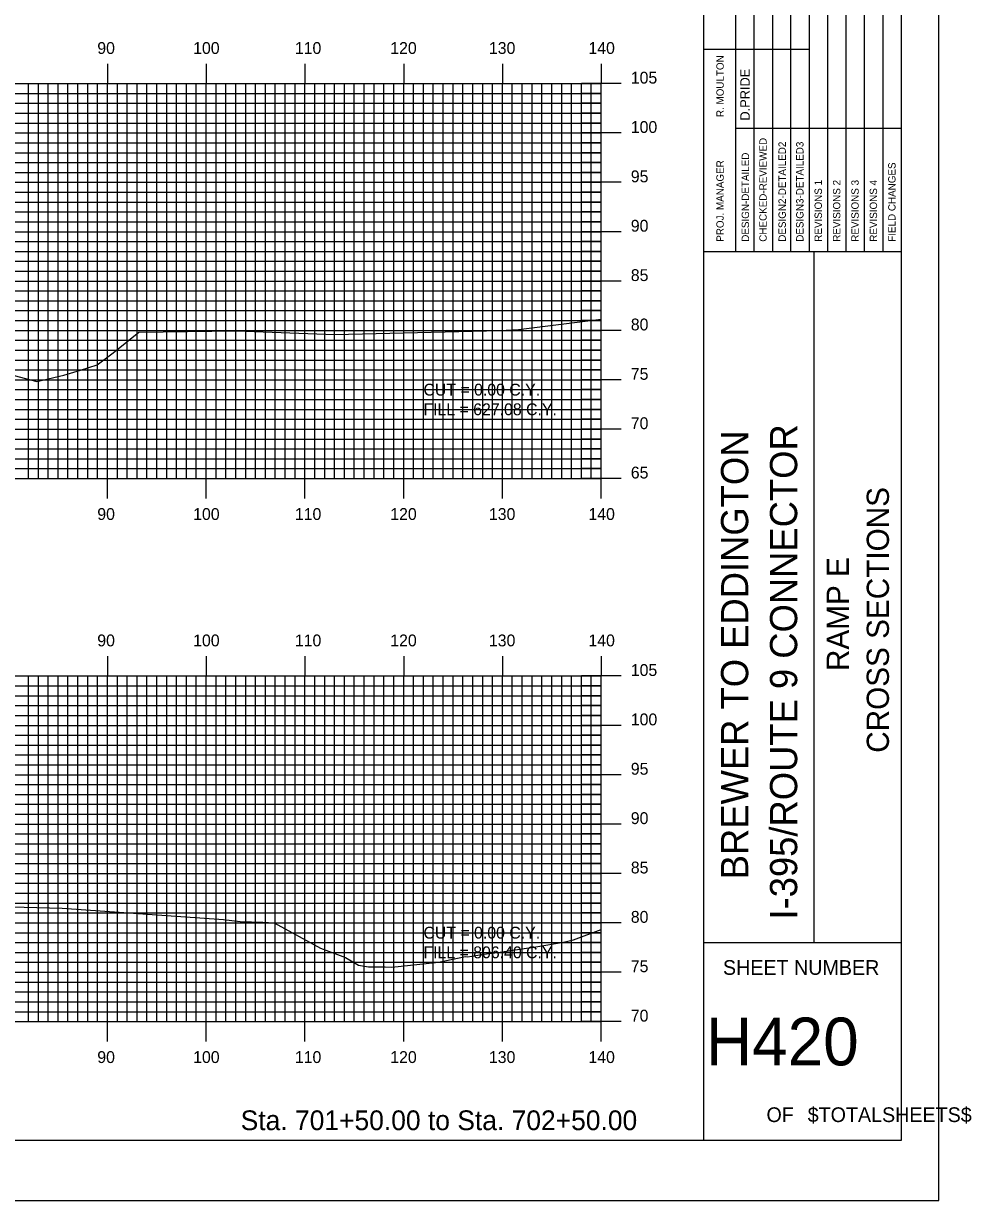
# Model space of a CAD drawing. Extents: x 852936 to 853279, y 364366 to 364586.
# Drawn here: x 853183.2 to 853279.2, y 364365.7 to 364484.9 of the extents above; entities that cross this region are included whole.
import ezdxf

# ---------------------------------------------------------------- set-up
doc = ezdxf.new("R2010")
doc.units = 0
for name, color, linetype in [('BORDER', 7, 'Continuous'), ('D_Text_Standard', 7, 'Continuous'), ('H_V ANNOTATION', 7, 'Continuous'), ('MAJOR', 7, 'Continuous'), ('MINOR', 7, 'Continuous'), ('PLOT BOUNDARY', 7, 'Continuous'), ('S_Roadway_Centerline', 7, 'Continuous')]:
    doc.layers.add(name, color=color, linetype=linetype)

msp = doc.modelspace()

# ---------------------------------------------------------------- linework, layer by layer
at = {"layer": 'BORDER'}
for p, q in [((853252.09, 364371.79), (853252.09, 364581.79)), ((853252.09, 364461.79), (853272.09, 364461.79)), ((853263.27, 364391.79), (853263.27, 364461.79)), ((853252.09, 364391.79), (853272.09, 364391.79))]:
    msp.add_line(p, q, dxfattribs=at)
msp.add_lwpolyline([(852952.09, 364371.79), (853272.09, 364371.79), (853272.09, 364581.79), (852952.09, 364581.79)], close=True, dxfattribs=at)
for points in [[(853257.19, 364461.8), (853257.19, 364496.79)], [(853259.05, 364496.79), (853259.05, 364461.8)], [(853260.91, 364461.8), (853260.91, 364496.79)], [(853262.78, 364461.8), (853262.78, 364496.79)], [(853264.64, 364461.8), (853264.64, 364496.79)], [(853266.5, 364461.8), (853266.5, 364496.79)], [(853268.37, 364461.8), (853268.37, 364496.79)], [(853270.23, 364461.8), (853270.23, 364496.79)], [(853255.32, 364461.8), (853255.32, 364495.38)], [(853252.09, 364482.29), (853255.32, 364482.29)], [(853255.32, 364482.29), (853262.77, 364482.29)], [(853255.32, 364474.29), (853272.09, 364474.29)]]:
    msp.add_lwpolyline(points, dxfattribs=at)
at = {"layer": 'MAJOR'}
for p, q in [((853191.69, 364480.79), (853191.69, 364478.79)), ((853201.69, 364480.79), (853201.69, 364478.79)), ((853211.69, 364480.79), (853211.69, 364478.79)), ((853221.69, 364480.79), (853221.69, 364478.79)), ((853231.69, 364480.79), (853231.69, 364478.79)), ((853241.69, 364480.79), (853241.69, 364478.79)), ((852961.69, 364478.79), (853241.69, 364478.79)), ((852961.69, 364478.79), (853241.69, 364478.79)), ((853191.69, 364438.79), (853191.69, 364478.79)), ((853201.69, 364438.79), (853201.69, 364478.79)), ((853211.69, 364438.79), (853211.69, 364478.79)), ((853221.69, 364438.79), (853221.69, 364478.79)), ((853231.69, 364438.79), (853231.69, 364478.79)), ((853243.7, 364478.79), (853239.69, 364478.79)), ((853241.69, 364438.79), (853241.69, 364478.79)), ((853241.69, 364438.79), (853241.69, 364478.79)), ((852961.69, 364473.79), (853241.69, 364473.79)), ((853243.7, 364473.79), (853239.69, 364473.79)), ((852961.69, 364468.79), (853241.69, 364468.79)), ((853243.7, 364468.79), (853239.69, 364468.79)), ((852961.69, 364463.79), (853241.69, 364463.79)), ((853243.7, 364463.79), (853239.69, 364463.79)), ((852961.69, 364458.79), (853241.69, 364458.79)), ((853243.7, 364458.79), (853239.69, 364458.79)), ((852961.69, 364453.79), (853241.69, 364453.79)), ((853243.7, 364453.79), (853239.69, 364453.79)), ((852961.69, 364448.79), (853241.69, 364448.79)), ((853243.7, 364448.79), (853239.69, 364448.79)), ((852961.69, 364443.79), (853241.69, 364443.79)), ((853243.7, 364443.79), (853239.69, 364443.79)), ((852961.69, 364438.79), (853241.69, 364438.79)), ((852961.69, 364438.79), (853241.69, 364438.79)), ((853191.69, 364436.78), (853191.69, 364438.79)), ((853201.69, 364436.78), (853201.69, 364438.79)), ((853211.69, 364436.78), (853211.69, 364438.79)), ((853221.69, 364436.78), (853221.69, 364438.79)), ((853231.69, 364436.78), (853231.69, 364438.79)), ((853243.7, 364438.79), (853239.69, 364438.79)), ((853241.69, 364436.78), (853241.69, 364438.79)), ((853191.69, 364420.79), (853191.69, 364418.79)), ((853201.69, 364420.79), (853201.69, 364418.79)), ((853211.69, 364420.79), (853211.69, 364418.79)), ((853221.69, 364420.79), (853221.69, 364418.79)), ((853231.69, 364420.79), (853231.69, 364418.79)), ((853241.69, 364420.79), (853241.69, 364418.79)), ((852961.69, 364418.79), (853241.69, 364418.79)), ((852961.69, 364418.79), (853241.69, 364418.79)), ((853191.69, 364383.79), (853191.69, 364418.79)), ((853201.69, 364383.79), (853201.69, 364418.79)), ((853211.69, 364383.79), (853211.69, 364418.79)), ((853221.69, 364383.79), (853221.69, 364418.79)), ((853231.69, 364383.79), (853231.69, 364418.79)), ((853243.7, 364418.79), (853239.69, 364418.79)), ((853241.69, 364383.79), (853241.69, 364418.79)), ((853241.69, 364383.79), (853241.69, 364418.79)), ((852961.69, 364413.79), (853241.69, 364413.79)), ((853243.7, 364413.79), (853239.69, 364413.79)), ((852961.69, 364408.79), (853241.69, 364408.79)), ((853243.7, 364408.79), (853239.69, 364408.79)), ((852961.69, 364403.79), (853241.69, 364403.79)), ((853243.7, 364403.79), (853239.69, 364403.79)), ((852961.69, 364398.79), (853241.69, 364398.79)), ((853243.7, 364398.79), (853239.69, 364398.79)), ((852961.69, 364393.79), (853241.69, 364393.79)), ((853243.7, 364393.79), (853239.69, 364393.79)), ((852961.69, 364388.79), (853241.69, 364388.79)), ((853243.7, 364388.79), (853239.69, 364388.79)), ((852961.69, 364383.79), (853241.69, 364383.79)), ((852961.69, 364383.79), (853241.69, 364383.79)), ((853191.69, 364381.78), (853191.69, 364383.79)), ((853201.69, 364381.78), (853201.69, 364383.79)), ((853211.69, 364381.78), (853211.69, 364383.79)), ((853221.69, 364381.78), (853221.69, 364383.79)), ((853231.69, 364381.78), (853231.69, 364383.79)), ((853243.7, 364383.79), (853239.69, 364383.79)), ((853241.69, 364381.78), (853241.69, 364383.79))]:
    msp.add_line(p, q, dxfattribs=at)
at = {"layer": 'MINOR'}
for p, q in [((853183.69, 364438.79), (853183.69, 364478.79)), ((853184.69, 364438.79), (853184.69, 364478.79)), ((853185.69, 364438.79), (853185.69, 364478.79)), ((853186.69, 364438.79), (853186.69, 364478.79)), ((853187.69, 364438.79), (853187.69, 364478.79)), ((853188.69, 364438.79), (853188.69, 364478.79)), ((853189.69, 364438.79), (853189.69, 364478.79)), ((853190.69, 364438.79), (853190.69, 364478.79)), ((853192.69, 364438.79), (853192.69, 364478.79)), ((853193.69, 364438.79), (853193.69, 364478.79)), ((853194.69, 364438.79), (853194.69, 364478.79)), ((853195.69, 364438.79), (853195.69, 364478.79)), ((853196.69, 364438.79), (853196.69, 364478.79)), ((853197.69, 364438.79), (853197.69, 364478.79)), ((853198.69, 364438.79), (853198.69, 364478.79)), ((853199.69, 364438.79), (853199.69, 364478.79)), ((853200.69, 364438.79), (853200.69, 364478.79)), ((853202.69, 364438.79), (853202.69, 364478.79)), ((853203.69, 364438.79), (853203.69, 364478.79)), ((853204.69, 364438.79), (853204.69, 364478.79)), ((853205.69, 364438.79), (853205.69, 364478.79)), ((853206.69, 364438.79), (853206.69, 364478.79)), ((853207.69, 364438.79), (853207.69, 364478.79)), ((853208.69, 364438.79), (853208.69, 364478.79)), ((853209.69, 364438.79), (853209.69, 364478.79)), ((853210.69, 364438.79), (853210.69, 364478.79)), ((853212.69, 364438.79), (853212.69, 364478.79)), ((853213.69, 364438.79), (853213.69, 364478.79)), ((853214.69, 364438.79), (853214.69, 364478.79)), ((853215.69, 364438.79), (853215.69, 364478.79)), ((853216.69, 364438.79), (853216.69, 364478.79)), ((853217.69, 364438.79), (853217.69, 364478.79)), ((853218.69, 364438.79), (853218.69, 364478.79)), ((853219.69, 364438.79), (853219.69, 364478.79)), ((853220.69, 364438.79), (853220.69, 364478.79)), ((853222.69, 364438.79), (853222.69, 364478.79)), ((853223.69, 364438.79), (853223.69, 364478.79)), ((853224.69, 364438.79), (853224.69, 364478.79)), ((853225.69, 364438.79), (853225.69, 364478.79)), ((853226.69, 364438.79), (853226.69, 364478.79)), ((853227.69, 364438.79), (853227.69, 364478.79)), ((853228.69, 364438.79), (853228.69, 364478.79)), ((853229.69, 364438.79), (853229.69, 364478.79)), ((853230.69, 364438.79), (853230.69, 364478.79)), ((853232.69, 364438.79), (853232.69, 364478.79)), ((853233.69, 364438.79), (853233.69, 364478.79)), ((853234.69, 364438.79), (853234.69, 364478.79)), ((853235.69, 364438.79), (853235.69, 364478.79)), ((853236.69, 364438.79), (853236.69, 364478.79)), ((853237.69, 364438.79), (853237.69, 364478.79)), ((853238.69, 364438.79), (853238.69, 364478.79)), ((853239.69, 364438.79), (853239.69, 364478.79)), ((853240.69, 364438.79), (853240.69, 364478.79)), ((852961.69, 364477.79), (853241.69, 364477.79)), ((852961.69, 364476.79), (853241.69, 364476.79)), ((853241.69, 364477.79), (853239.69, 364477.79)), ((853241.69, 364476.79), (853239.69, 364476.79)), ((852961.69, 364475.79), (853241.69, 364475.79)), ((853241.69, 364475.79), (853239.69, 364475.79)), ((852961.69, 364474.79), (853241.69, 364474.79)), ((853241.69, 364474.79), (853239.69, 364474.79)), ((852961.69, 364472.79), (853241.69, 364472.79)), ((853241.69, 364472.79), (853239.69, 364472.79)), ((852961.69, 364471.79), (853241.69, 364471.79)), ((852961.69, 364470.79), (853241.69, 364470.79)), ((853241.69, 364471.79), (853239.69, 364471.79)), ((853241.69, 364470.79), (853239.69, 364470.79)), ((852961.69, 364469.79), (853241.69, 364469.79)), ((853241.69, 364469.79), (853239.69, 364469.79)), ((852961.69, 364467.79), (853241.69, 364467.79)), ((853241.69, 364467.79), (853239.69, 364467.79)), ((852961.69, 364466.79), (853241.69, 364466.79)), ((853241.69, 364466.79), (853239.69, 364466.79)), ((852961.69, 364465.79), (853241.69, 364465.79)), ((853241.69, 364465.79), (853239.69, 364465.79)), ((852961.69, 364464.79), (853241.69, 364464.79)), ((853241.69, 364464.79), (853239.69, 364464.79)), ((852961.69, 364462.79), (853241.69, 364462.79)), ((853241.69, 364462.79), (853239.69, 364462.79)), ((852961.69, 364461.79), (853241.69, 364461.79)), ((853241.69, 364461.79), (853239.69, 364461.79)), ((852961.69, 364460.79), (853241.69, 364460.79)), ((853241.69, 364460.79), (853239.69, 364460.79)), ((852961.69, 364459.79), (853241.69, 364459.79)), ((853241.69, 364459.79), (853239.69, 364459.79)), ((852961.69, 364457.79), (853241.69, 364457.79)), ((853241.69, 364457.79), (853239.69, 364457.79)), ((852961.69, 364456.79), (853241.69, 364456.79)), ((853241.69, 364456.79), (853239.69, 364456.79)), ((852961.69, 364455.79), (853241.69, 364455.79)), ((853241.69, 364455.79), (853239.69, 364455.79)), ((852961.69, 364454.79), (853241.69, 364454.79)), ((853241.69, 364454.79), (853239.69, 364454.79)), ((852961.69, 364452.79), (853241.69, 364452.79)), ((852961.69, 364451.79), (853241.69, 364451.79)), ((853241.69, 364452.79), (853239.69, 364452.79)), ((853241.69, 364451.79), (853239.69, 364451.79)), ((852961.69, 364450.79), (853241.69, 364450.79)), ((853241.69, 364450.79), (853239.69, 364450.79)), ((852961.69, 364449.79), (853241.69, 364449.79)), ((853241.69, 364449.79), (853239.69, 364449.79)), ((852961.69, 364447.79), (853241.69, 364447.79)), ((853241.69, 364447.79), (853239.69, 364447.79)), ((852961.69, 364446.79), (853241.69, 364446.79)), ((852961.69, 364445.79), (853241.69, 364445.79)), ((853241.69, 364446.79), (853239.69, 364446.79)), ((853241.69, 364445.79), (853239.69, 364445.79)), ((852961.69, 364444.79), (853241.69, 364444.79)), ((853241.69, 364444.79), (853239.69, 364444.79)), ((852961.69, 364442.79), (853241.69, 364442.79)), ((853241.69, 364442.79), (853239.69, 364442.79)), ((852961.69, 364441.79), (853241.69, 364441.79)), ((853241.69, 364441.79), (853239.69, 364441.79)), ((852961.69, 364440.79), (853241.69, 364440.79)), ((853241.69, 364440.79), (853239.69, 364440.79)), ((852961.69, 364439.79), (853241.69, 364439.79)), ((853241.69, 364439.79), (853239.69, 364439.79)), ((853183.69, 364383.79), (853183.69, 364418.79)), ((853184.69, 364383.79), (853184.69, 364418.79)), ((853185.69, 364383.79), (853185.69, 364418.79)), ((853186.69, 364383.79), (853186.69, 364418.79)), ((853187.69, 364383.79), (853187.69, 364418.79)), ((853188.69, 364383.79), (853188.69, 364418.79)), ((853189.69, 364383.79), (853189.69, 364418.79)), ((853190.69, 364383.79), (853190.69, 364418.79)), ((853192.69, 364383.79), (853192.69, 364418.79)), ((853193.69, 364383.79), (853193.69, 364418.79)), ((853194.69, 364383.79), (853194.69, 364418.79)), ((853195.69, 364383.79), (853195.69, 364418.79)), ((853196.69, 364383.79), (853196.69, 364418.79)), ((853197.69, 364383.79), (853197.69, 364418.79)), ((853198.69, 364383.79), (853198.69, 364418.79)), ((853199.69, 364383.79), (853199.69, 364418.79)), ((853200.69, 364383.79), (853200.69, 364418.79)), ((853202.69, 364383.79), (853202.69, 364418.79)), ((853203.69, 364383.79), (853203.69, 364418.79)), ((853204.69, 364383.79), (853204.69, 364418.79)), ((853205.69, 364383.79), (853205.69, 364418.79)), ((853206.69, 364383.79), (853206.69, 364418.79)), ((853207.69, 364383.79), (853207.69, 364418.79)), ((853208.69, 364383.79), (853208.69, 364418.79)), ((853209.69, 364383.79), (853209.69, 364418.79)), ((853210.69, 364383.79), (853210.69, 364418.79)), ((853212.69, 364383.79), (853212.69, 364418.79)), ((853213.69, 364383.79), (853213.69, 364418.79)), ((853214.69, 364383.79), (853214.69, 364418.79)), ((853215.69, 364383.79), (853215.69, 364418.79)), ((853216.69, 364383.79), (853216.69, 364418.79)), ((853217.69, 364383.79), (853217.69, 364418.79)), ((853218.69, 364383.79), (853218.69, 364418.79)), ((853219.69, 364383.79), (853219.69, 364418.79)), ((853220.69, 364383.79), (853220.69, 364418.79)), ((853222.69, 364383.79), (853222.69, 364418.79)), ((853223.69, 364383.79), (853223.69, 364418.79)), ((853224.69, 364383.79), (853224.69, 364418.79)), ((853225.69, 364383.79), (853225.69, 364418.79)), ((853226.69, 364383.79), (853226.69, 364418.79)), ((853227.69, 364383.79), (853227.69, 364418.79)), ((853228.69, 364383.79), (853228.69, 364418.79)), ((853229.69, 364383.79), (853229.69, 364418.79)), ((853230.69, 364383.79), (853230.69, 364418.79)), ((853232.69, 364383.79), (853232.69, 364418.79)), ((853233.69, 364383.79), (853233.69, 364418.79)), ((853234.69, 364383.79), (853234.69, 364418.79)), ((853235.69, 364383.79), (853235.69, 364418.79)), ((853236.69, 364383.79), (853236.69, 364418.79)), ((853237.69, 364383.79), (853237.69, 364418.79)), ((853238.69, 364383.79), (853238.69, 364418.79)), ((853239.69, 364383.79), (853239.69, 364418.79)), ((853240.69, 364383.79), (853240.69, 364418.79)), ((852961.69, 364417.79), (853241.69, 364417.79)), ((853241.69, 364417.79), (853239.69, 364417.79)), ((852961.69, 364416.79), (853241.69, 364416.79)), ((853241.69, 364416.79), (853239.69, 364416.79)), ((852961.69, 364415.79), (853241.69, 364415.79)), ((852961.69, 364414.79), (853241.69, 364414.79)), ((853241.69, 364415.79), (853239.69, 364415.79)), ((853241.69, 364414.79), (853239.69, 364414.79)), ((852961.69, 364412.79), (853241.69, 364412.79)), ((853241.69, 364412.79), (853239.69, 364412.79)), ((852961.69, 364411.79), (853241.69, 364411.79)), ((853241.69, 364411.79), (853239.69, 364411.79)), ((852961.69, 364410.79), (853241.69, 364410.79)), ((853241.69, 364410.79), (853239.69, 364410.79)), ((852961.69, 364409.79), (853241.69, 364409.79)), ((853241.69, 364409.79), (853239.69, 364409.79)), ((852961.69, 364407.79), (853241.69, 364407.79)), ((853241.69, 364407.79), (853239.69, 364407.79)), ((852961.69, 364406.79), (853241.69, 364406.79)), ((853241.69, 364406.79), (853239.69, 364406.79)), ((852961.69, 364405.79), (853241.69, 364405.79)), ((853241.69, 364405.79), (853239.69, 364405.79)), ((852961.69, 364404.79), (853241.69, 364404.79)), ((853241.69, 364404.79), (853239.69, 364404.79)), ((852961.69, 364402.79), (853241.69, 364402.79)), ((852961.69, 364401.79), (853241.69, 364401.79)), ((853241.69, 364402.79), (853239.69, 364402.79)), ((853241.69, 364401.79), (853239.69, 364401.79)), ((852961.69, 364400.79), (853241.69, 364400.79)), ((853241.69, 364400.79), (853239.69, 364400.79)), ((852961.69, 364399.79), (853241.69, 364399.79)), ((853241.69, 364399.79), (853239.69, 364399.79)), ((852961.69, 364397.79), (853241.69, 364397.79)), ((853241.69, 364397.79), (853239.69, 364397.79)), ((852961.69, 364396.79), (853241.69, 364396.79)), ((852961.69, 364395.79), (853241.69, 364395.79)), ((853241.69, 364396.79), (853239.69, 364396.79)), ((853241.69, 364395.79), (853239.69, 364395.79)), ((852961.69, 364394.79), (853241.69, 364394.79)), ((853241.69, 364394.79), (853239.69, 364394.79)), ((852961.69, 364392.79), (853241.69, 364392.79)), ((853241.69, 364392.79), (853239.69, 364392.79)), ((852961.69, 364391.79), (853241.69, 364391.79)), ((853241.69, 364391.79), (853239.69, 364391.79)), ((852961.69, 364390.79), (853241.69, 364390.79)), ((852961.69, 364389.79), (853241.69, 364389.79)), ((853241.69, 364390.79), (853239.69, 364390.79)), ((853241.69, 364389.79), (853239.69, 364389.79)), ((852961.69, 364387.79), (853241.69, 364387.79)), ((853241.69, 364387.79), (853239.69, 364387.79)), ((852961.69, 364386.79), (853241.69, 364386.79)), ((853241.69, 364386.79), (853239.69, 364386.79)), ((852961.69, 364385.79), (853241.69, 364385.79)), ((853241.69, 364385.79), (853239.69, 364385.79)), ((852961.69, 364384.79), (853241.69, 364384.79)), ((853241.69, 364384.79), (853239.69, 364384.79))]:
    msp.add_line(p, q, dxfattribs=at)
at = {"layer": 'PLOT BOUNDARY'}
msp.add_lwpolyline([(852935.9, 364365.67), (853275.9, 364365.67), (853275.9, 364585.67), (852935.9, 364585.67)], close=True, dxfattribs=at)
at = {"layer": 'S_Roadway_Centerline'}
for points in [[(853178.25, 364450.28), (853184.55, 364448.63), (853187.27, 364449.26), (853188.97, 364449.77), (853190.66, 364450.3), (853192.26, 364451.52), (853194.88, 364453.6), (853204.71, 364453.74), (853214.72, 364453.39), (853231.46, 364453.78), (853233.31, 364453.87), (853241.69, 364454.94)], [(853175.55, 364395.58), (853187.11, 364395.26), (853203.44, 364394.11), (853205.14, 364393.93), (853207.44, 364393.86), (853208.58, 364393.78), (853213.26, 364391.23), (853215.79, 364390.29), (853217.11, 364389.51), (853218.13, 364389.34), (853219.81, 364389.34), (853220.48, 364389.31), (853225.22, 364389.79), (853227.94, 364390.37), (853228.14, 364390.35), (853228.58, 364390.41), (853229.81, 364390.62), (853231.47, 364390.83), (853232.5, 364391), (853235.06, 364391.35), (853237.88, 364391.84), (853238.88, 364392.06), (853241.69, 364393.12)]]:
    msp.add_lwpolyline(points, dxfattribs=at)

# ---------------------------------------------------------------- texts
at = {"layer": 'BORDER'}
for s, height, p in [('R. MOULTON', 0.745, (853254.1, 364475.4)), ('D.PRIDE', 0.969, (853256.74, 364475.04)), ('CHECKED-REVIEWED', 0.7455, (853258.45, 364462.77)), ('DESIGN2-DETAILED2', 0.7455, (853260.39, 364462.77)), ('DESIGN3-DETAILED3', 0.7455, (853262.18, 364462.77)), ('PROJ. MANAGER', 0.7455, (853254.1, 364462.77)), ('DESIGN-DETAILED', 0.7455, (853256.66, 364462.77)), ('FIELD CHANGES', 0.7455, (853271.5, 364462.77)), ('REVISIONS 1', 0.7455, (853264.04, 364462.77)), ('REVISIONS 2', 0.7455, (853265.91, 364462.77)), ('REVISIONS 3', 0.7455, (853267.77, 364462.77)), ('REVISIONS 4', 0.7455, (853269.63, 364462.77)), ('I-395/ROUTE 9 CONNECTOR', 2.7557, (853261.54, 364394.12)), ('BREWER TO EDDINGTON', 2.7557, (853256.58, 364398.2)), ('CROSS SECTIONS', 2.25, (853270.83, 364411.01)), ('RAMP E', 2.25, (853266.78, 364419.29))]:
    msp.add_text(s, height=height, rotation=90, dxfattribs=at).set_placement(p)
for s, height, p in [('SHEET NUMBER', 1.4905, (853254.02, 364388.52)), ('H420', 4.839, (853252.3, 364379.35)), ('OF', 1.491, (853258.43, 364373.61)), ('$TOTALSHEETS$', 1.4905, (853262.6, 364373.61))]:
    msp.add_text(s, height=height, dxfattribs=at).set_placement(p)
at = {"layer": 'D_Text_Standard'}
for s, p in [('CUT = 0.00 C.Y.', (853223.69, 364447.19)), ('FILL = 627.08 C.Y.', (853223.69, 364445.2)), ('CUT = 0.00 C.Y.', (853223.69, 364392.19)), ('FILL = 806.40 C.Y.', (853223.69, 364390.2))]:
    msp.add_text(s, height=1.2, dxfattribs=at).set_placement(p)
at = {"layer": 'H_V ANNOTATION'}
for s, height, p in [('90', 1.2, (853190.66, 364481.79)), ('100', 1.2, (853200.37, 364481.79)), ('110', 1.2, (853210.67, 364481.79)), ('120', 1.2, (853220.33, 364481.79)), ('130', 1.2, (853230.32, 364481.79)), ('140', 1.2, (853240.4, 364481.79)), ('105', 1.2, (853244.69, 364478.79)), ('100', 1.2, (853244.69, 364473.79)), ('95', 1.2, (853244.69, 364468.79)), ('90', 1.2, (853244.69, 364463.79)), ('85', 1.2, (853244.69, 364458.79)), ('80', 1.2, (853244.69, 364453.79)), ('75', 1.2, (853244.69, 364448.79)), ('70', 1.2, (853244.69, 364443.79)), ('65', 1.2, (853244.69, 364438.79)), ('90', 1.2, (853190.66, 364434.59)), ('100', 1.2, (853200.37, 364434.59)), ('110', 1.2, (853210.67, 364434.59)), ('120', 1.2, (853220.33, 364434.59)), ('130', 1.2, (853230.32, 364434.59)), ('140', 1.2, (853240.4, 364434.59)), ('90', 1.2, (853190.66, 364421.79)), ('100', 1.2, (853200.37, 364421.79)), ('110', 1.2, (853210.67, 364421.79)), ('120', 1.2, (853220.33, 364421.79)), ('130', 1.2, (853230.32, 364421.79)), ('140', 1.2, (853240.4, 364421.79)), ('105', 1.2, (853244.69, 364418.79)), ('100', 1.2, (853244.69, 364413.79)), ('95', 1.2, (853244.69, 364408.79)), ('90', 1.2, (853244.69, 364403.79)), ('85', 1.2, (853244.69, 364398.79)), ('80', 1.2, (853244.69, 364393.79)), ('75', 1.2, (853244.69, 364388.79)), ('70', 1.2, (853244.69, 364383.79)), ('90', 1.2, (853190.66, 364379.59)), ('100', 1.2, (853200.37, 364379.59)), ('110', 1.2, (853210.67, 364379.59)), ('120', 1.2, (853220.33, 364379.59)), ('130', 1.2, (853230.32, 364379.59)), ('140', 1.2, (853240.4, 364379.59)), ('Sta. 701+50.00 to Sta. 702+50.00', 2.0004, (853205.18, 364372.79))]:
    msp.add_text(s, height=height, dxfattribs=at).set_placement(p)

doc.saveas('drawing.dxf')
